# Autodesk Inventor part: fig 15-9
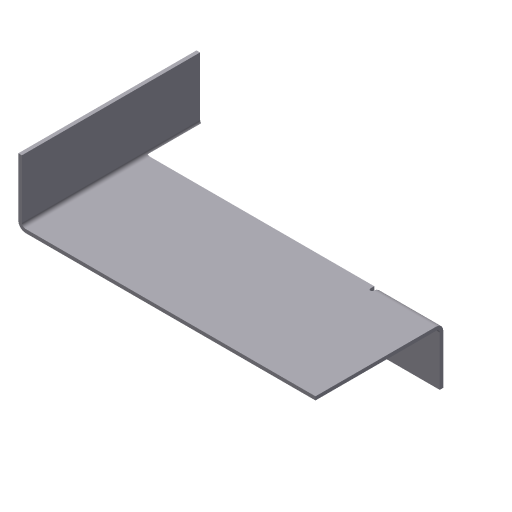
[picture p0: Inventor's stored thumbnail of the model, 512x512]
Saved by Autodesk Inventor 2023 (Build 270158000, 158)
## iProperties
Created: 2002-04
Part Number: fig 15-9
Material: Aluminum-6061
Document SubType Name: Sheet Metal
Density: 1 g/cm^3
Sheet Metal Rule: Default
Appearance: Aluminum - Flat-1
Control State: 0
Master: False
Checked Out: False
Shininess: 77.0
Angle Display Precision: 2
Document Length Units: 11269
Document Angle Units: 11279
Document Time Units: 11290
Document Mass Units: 11283
Document Length Units Precision: 3
Document Angle Units Precision: 2
Density: 0.0
Volumn: 0.0
Area: 0.0
PropertySet Name: Model Information
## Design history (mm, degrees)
node "Face1"
  sketch "Sketch1"
    geometry: L1 (-49.559, 19.574)-(-49.559, -30.426); L2 (-49.559, -30.426)-(50.441, -30.426); L3 (50.441, -30.426)-(50.441, 19.574); L4 (50.441, 19.574)-(32.941, 19.574); L5 (32.941, 19.574)-(32.941, 4.574); L6 (32.941, 4.574)-(-32.059, 4.574); L7 (-32.059, 4.574)-(-32.059, 19.574); L8 (-32.059, 19.574)-(-49.559, 19.574)
    constraints: 16 end point, 6 parallel, 2 equal length, 1 perpendicular, 1 vertical
    dimensions: "d0" = 100 distance of L1.end L2.end; "d1" = 65 distance of L5.end L6.end; "d2" = 15 distance of L6.end L7.end; "d3" = 50 distance of L1.start L1.end
sketch "Sketch2"
  geometry: L1 (100, 0)-(0, 0) reference; L2 (17.5, 50)-(17.5, 35) reference; L3 (82.5, 50)-(82.5, 0)
  constraints: 2 end point, 1 parallel, 1 point on line
sketch "Sketch3"
  geometry: L1 (81.369, -50)-(0, -50) reference; L2 (17.5, 0)-(17.5, -50)
  constraints: 2 end point, 1 perpendicular, 1 point on line
feature "Fold2" sketch "Sketch3" dims "d8" = 1 (= BendRadius), "d9" = 90 deg, "d10" = 1 (= BendRadius), "d14" = 1 (= BendReliefWidth), "d15" = 0.5 (= BendReliefDepth), "d16" = 2 (= MinimumRemnant), "d20" = 1 (= Thickness), "SeamGap" = 0.01
sketch "Sketch4"
  geometry: L1 (17.5, 0)-(17.5, -50) reference; L2 (-63.869, -15)-(0, -15) reference; L3 (0, -15)-(17.5, -15)
  constraints: 2 end point, 1 collinear, 1 point on line
feature "Fold3" sketch "Sketch4" dims "d11" = 1 (= BendRadius), "d12" = 90 deg, "d13" = 1 (= BendRadius), "d17" = 1 (= BendReliefWidth), "d18" = 0.5 (= BendReliefDepth), "d19" = 2 (= MinimumRemnant), "d20" = 1 (= Thickness), "SeamGap" = 0.01
body "Solid1"
face "Plate1" dims "d20" = 1 (= Thickness)
other parameters: "Thickness" = 1, "BendRadius" = 1 (= Thickness), "BendReliefWidth" = 1 (= Thickness), "BendReliefDepth" = 0.5 (= 0.5 x Thickness), "CornerReliefSize" = 4 (= 4 x Thickness), "MinimumRemnant" = 2 (= 2 x Thickness), "TransitionRadius" = 1 (= BendRadius), "d4" = 1 (= BendRadius), "JacobiRadiusSize" = 1 (= Thickness), "GapSize" = 1 (= Thickness)
